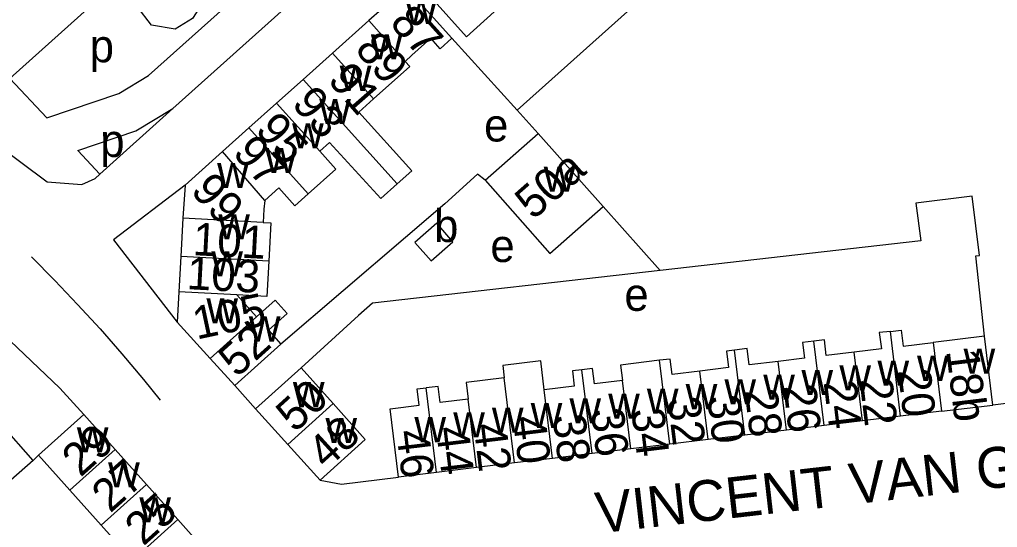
# Model space of a CAD drawing. Extents: x 161775 to 163181, y 382878 to 383925.
# Drawn here: x 162735.4 to 162855, y 383267.3 to 383329.4 of the extents above; entities that cross this region are included whole.
import ezdxf

# ---------------------------------------------------------------- set-up
doc = ezdxf.new("R2010")
doc.units = 0
for name, color, linetype in [('BLT_Basislijn', 7, 'Continuous'), ('BLT_Bebouwing', 7, 'Continuous'), ('BLT_Centroide', 7, 'Continuous'), ('BLT_Huisnummer', 7, 'Continuous'), ('BLT_Huisnummer_ tussenligend', 7, 'Continuous'), ('BLT_Onderverdeling_panden', 7, 'Continuous'), ('BLT_Straatnaam', 7, 'Continuous')]:
    doc.layers.add(name, color=color, linetype=linetype)

msp = doc.modelspace()

# ---------------------------------------------------------------- linework, layer by layer
at = {"layer": 'BLT_Basislijn'}
for p, q in [((162796.22, 383318.34), (162857.79, 383373.53)), ((162751.13, 383322.57), (162767.53, 383337.28)), ((162734.18, 383322.22), (162747.65, 383334.31)), ((162754.11, 383318.53), (162771.38, 383334.03)), ((162796.22, 383318.34), (162788.22, 383327.14)), ((162734.18, 383322.22), (162738.71, 383317.41)), ((162745.19, 383310.52), (162754.11, 383318.53)), ((162798.8, 383315.5), (162796.22, 383318.34)), ((162742.48, 383313.4), (162745.19, 383310.52)), ((162744.61, 383310), (162745.19, 383310.52)), ((162792.31, 383309.78), (162791.36, 383310.5)), ((162806.75, 383306.55), (162813.73, 383298.72)), ((162776.82, 383293.21), (162769.8, 383286.82)), ((162764.23, 383281.8), (162761.68, 383284.66)), ((162861.08, 383283.08), (162854.42, 383282.27)), ((162737.68, 383276.13), (162737.02, 383275.48))]:
    msp.add_line(p, q, dxfattribs=at)
for points in [[(162762.22, 383347.39), (162765.35, 383344.2), (162765.81, 383341.08), (162763.37, 383335.52), (162762.16, 383333.95), (162760.51, 383332.85), (162759.35, 383332.56), (162757.88, 383331.64), (162756.53, 383329.54), (162754.39, 383328.24), (162751.51, 383328.73), (162749.75, 383331.04), (162747.65, 383334.31)], [(162738.71, 383317.41), (162747.49, 383320.39), (162751.13, 383322.57)], [(162732.32, 383320.55), (162731.35, 383318.86), (162732.27, 383314.38), (162738.74, 383309.56), (162742.97, 383309.23)], [(162742.48, 383313.4), (162749.6, 383315.82), (162754.11, 383318.53)], [(162791.36, 383310.5), (162787.37, 383306.9), (162782.58, 383302.75), (162767.34, 383289.73)], [(162742.97, 383309.23), (162744.61, 383310)], [(162755.6, 383309.17), (162746.86, 383302.49), (162754.64, 383292.41)], [(162853.39, 383290.69), (162852.32, 383300.52), (162852.76, 383300.57), (162851.87, 383307.83), (162844.97, 383306.97), (162845.61, 383302.36), (162813.73, 383298.72)], [(162736.81, 383300.4), (162739.67, 383297.51), (162742.47, 383294.57), (162745.21, 383291.57), (162747.89, 383288.51), (162750.51, 383285.41), (162752.57, 383282.87)], [(162813.73, 383298.72), (162778.52, 383294.73), (162776.82, 383293.21)], [(162730.7, 383293.41), (162740.29, 383284.35), (162743.22, 383281.09)], [(162772.15, 383273.06), (162774.76, 383272.58), (162781.73, 383273.46)]]:
    msp.add_lwpolyline(points, dxfattribs=at)
at = {"layer": 'BLT_Bebouwing'}
for p, q in [((162790.02, 383327.33), (162783.75, 383334.33)), ((162782.64, 383333.39), (162778.08, 383329.31)), ((162788.22, 383327.14), (162782.64, 383333.39)), ((162794.67, 383331.51), (162790.02, 383327.33)), ((162778.08, 383329.31), (162773.63, 383325.32)), ((162773.63, 383325.32), (162770.04, 383322.1)), ((162770.04, 383322.1), (162766.79, 383319.2)), ((162766.79, 383319.2), (162763.41, 383316.17)), ((162763.41, 383316.17), (162760.17, 383313.27)), ((162792.31, 383309.78), (162798.8, 383315.5)), ((162798.8, 383315.5), (162806.75, 383306.55)), ((162792.31, 383309.78), (162800.22, 383300.8)), ((162800.22, 383300.8), (162806.75, 383306.55)), ((162755.34, 383305.12), (162755.09, 383300.43)), ((162755.09, 383300.43), (162754.85, 383296.11)), ((162754.85, 383296.11), (162754.64, 383292.41)), ((162761.93, 383295.74), (162764.36, 383293.05)), ((162754.64, 383292.41), (162758.69, 383287.95)), ((162853.39, 383290.69), (162847.11, 383289.91)), ((162854.42, 383282.27), (162853.39, 383290.69)), ((162761.68, 383284.66), (162767.34, 383289.73)), ((162758.69, 383287.95), (162761.68, 383284.66)), ((162764.23, 383281.8), (162769.8, 383286.82)), ((162769.8, 383286.82), (162773.71, 383282.46)), ((162768.19, 383277.43), (162764.23, 383281.8)), ((162848.13, 383281.51), (162843.12, 383280.9)), ((162848.13, 383281.51), (162854.42, 383282.27)), ((162737.68, 383276.13), (162743.22, 383281.09)), ((162743.22, 383281.09), (162747.05, 383276.82)), ((162838.46, 383280.33), (162833.79, 383279.77)), ((162843.12, 383280.9), (162838.46, 383280.33)), ((162829.16, 383279.21), (162824.07, 383278.59)), ((162833.79, 383279.77), (162829.16, 383279.21)), ((162819.58, 383278.04), (162814.9, 383277.48)), ((162824.07, 383278.59), (162819.58, 383278.04)), ((162747.05, 383276.82), (162750.88, 383272.54)), ((162772.15, 383273.06), (162768.19, 383277.43)), ((162810.11, 383276.9), (162805.38, 383276.32)), ((162814.9, 383277.48), (162810.11, 383276.9)), ((162741.51, 383271.86), (162737.68, 383276.13)), ((162800.56, 383275.74), (162795.92, 383275.18)), ((162805.38, 383276.32), (162800.56, 383275.74)), ((162791.24, 383274.61), (162786.37, 383274.02)), ((162795.92, 383275.18), (162791.24, 383274.61)), ((162786.37, 383274.02), (162781.73, 383273.46)), ((162750.88, 383272.54), (162754.71, 383268.26)), ((162745.34, 383267.58), (162741.51, 383271.86)), ((162749.17, 383263.3), (162745.34, 383267.58)), ((162754.71, 383268.26), (162758.54, 383263.98))]:
    msp.add_line(p, q, dxfattribs=at)
for points in [[(162788.22, 383327.14), (162786.81, 383325.86), (162785.68, 383327.14), (162783.36, 383325.05)], [(162783.36, 383325.05), (162782.54, 383324.31)], [(162782.54, 383324.31), (162783.08, 383323.7), (162778.66, 383319.73)], [(162778.66, 383319.73), (162776.87, 383318.11), (162783.34, 383310.93), (162781.54, 383309.31)], [(162781.54, 383309.31), (162779.56, 383307.52), (162773.27, 383314.38), (162772.08, 383313.31)], [(162760.17, 383313.27), (162755.6, 383309.17)], [(162772.08, 383313.31), (162774.04, 383311.14), (162770.67, 383308.1)], [(162755.6, 383309.17), (162755.34, 383305.12)], [(162770.67, 383308.1), (162769.04, 383306.64), (162767.08, 383308.83), (162765.37, 383307.29)], [(162765.37, 383307.29), (162765.24, 383306.23), (162765.16, 383304.61)], [(162765.16, 383304.61), (162766.09, 383304.56), (162765.84, 383299.86)], [(162765.84, 383299.86), (162765.61, 383295.54), (162761.93, 383295.74)], [(162764.36, 383293.05), (162766.63, 383295.09), (162768.09, 383293.46), (162765.82, 383291.42), (162767.34, 383289.73)], [(162841.87, 383291.28), (162840.52, 383291.12), (162840.77, 383289.14), (162837.43, 383288.73)], [(162841.87, 383291.28), (162843.19, 383291.44), (162843.43, 383289.47), (162847.11, 383289.91)], [(162832.53, 383290.1), (162831.12, 383289.93), (162831.36, 383287.99), (162828.14, 383287.6)], [(162837.43, 383288.73), (162834.03, 383288.32), (162833.8, 383290.25), (162832.53, 383290.1)], [(162822.8, 383288.99), (162821.83, 383288.87), (162822.07, 383286.86), (162818.56, 383286.43)], [(162828.14, 383287.6), (162824.61, 383287.17), (162824.36, 383289.18), (162822.8, 383288.99)], [(162799.54, 383284.11), (162799.11, 383287.66), (162794.47, 383287.1), (162794.65, 383285.59)], [(162813.65, 383287.74), (162808.86, 383287.15), (162809.09, 383285.28)], [(162818.56, 383286.43), (162815.17, 383286.02), (162814.94, 383287.89), (162813.65, 383287.74)], [(162804.13, 383286.58), (162802.98, 383286.44), (162803.21, 383284.56), (162799.54, 383284.11)], [(162809.09, 383285.28), (162805.67, 383284.86), (162805.44, 383286.74), (162804.13, 383286.58)], [(162794.65, 383285.59), (162789.97, 383285.02), (162790.22, 383282.98)], [(162781.73, 383273.46), (162780.71, 383281.82), (162784.23, 383282.25), (162783.99, 383284.23), (162785.1, 383284.37)], [(162790.22, 383282.98), (162786.79, 383282.56), (162786.55, 383284.55), (162785.1, 383284.37)], [(162773.71, 383282.46), (162777.65, 383278.07), (162772.15, 383273.06)], [(162737.02, 383275.48), (162733.14, 383279.88), (162732.2, 383279.1), (162726.19, 383278.83), (162724.44, 383277.29), (162723.16, 383278.8), (162722.03, 383277.81)], [(162737.02, 383275.48), (162733.27, 383272.17), (162728.26, 383267.75)]]:
    msp.add_lwpolyline(points, dxfattribs=at)
msp.add_lwpolyline([(162786.4, 383304.52), (162783.72, 383302.14), (162785.71, 383299.9), (162788.37, 383302.25)], close=True, dxfattribs=at)
at = {"layer": 'BLT_Onderverdeling_panden'}
for p, q in [((162782.54, 383324.31), (162778.08, 383329.31)), ((162778.66, 383319.73), (162773.63, 383325.32)), ((162781.54, 383309.31), (162770.04, 383322.1)), ((162772.08, 383313.31), (162766.79, 383319.2)), ((162770.67, 383308.1), (162763.41, 383316.17)), ((162765.37, 383307.29), (162760.17, 383313.27)), ((162765.16, 383304.61), (162755.34, 383305.12)), ((162765.84, 383299.86), (162755.09, 383300.43)), ((162761.93, 383295.74), (162754.85, 383296.11)), ((162764.36, 383293.05), (162758.69, 383287.95)), ((162843.12, 383280.9), (162841.87, 383291.28)), ((162833.79, 383279.77), (162832.53, 383290.1)), ((162847.11, 383289.91), (162848.13, 383281.51)), ((162824.07, 383278.59), (162822.8, 383288.99)), ((162838.46, 383280.33), (162837.43, 383288.73)), ((162814.9, 383277.48), (162813.65, 383287.74)), ((162829.16, 383279.21), (162828.14, 383287.6)), ((162805.38, 383276.32), (162804.13, 383286.58)), ((162819.58, 383278.04), (162818.56, 383286.43)), ((162795.92, 383275.18), (162794.65, 383285.59)), ((162810.11, 383276.9), (162809.09, 383285.28)), ((162786.37, 383274.02), (162785.1, 383284.37)), ((162800.56, 383275.74), (162799.54, 383284.11)), ((162791.24, 383274.61), (162790.22, 383282.98)), ((162773.71, 383282.46), (162768.19, 383277.43)), ((162741.51, 383271.86), (162747.05, 383276.82)), ((162745.34, 383267.58), (162750.88, 383272.54)), ((162749.17, 383263.3), (162754.71, 383268.26))]:
    msp.add_line(p, q, dxfattribs=at)

# ---------------------------------------------------------------- texts
at = {"layer": 'BLT_Centroide'}
for s, p in [('w', (162782.55, 383328.88)), ('p', (162743.94, 383324.2)), ('w', (162778.33, 383324.56)), ('w', (162774.53, 383320.7)), ('w', (162772.02, 383316.64)), ('e', (162792.18, 383314.51)), ('w', (162768.7, 383313.67)), ('p', (162745.23, 383312.61)), ('w', (162765.41, 383310.64)), ('w', (162759.53, 383308.81)), ('w', (162799.47, 383308.36)), ('w', (162759.67, 383302.53)), ('b', (162786.06, 383302.21)), ('e', (162792.95, 383299.76)), ('w', (162758.82, 383298)), ('e', (162809.34, 383293.79)), ('w', (162758.22, 383292.25)), ('w', (162763.41, 383290.03)), ('w', (162850.83, 383286.09)), ('w', (162840.3, 383284.62)), ('w', (162845.14, 383285.22)), ('w', (162831, 383283.48)), ('w', (162835.64, 383284.05)), ('w', (162821.58, 383282.34)), ('w', (162826.33, 383282.91)), ('w', (162768.8, 383282)), ('w', (162812.09, 383281.19)), ('w', (162816.84, 383281.75)), ('w', (162802.62, 383280.03)), ('w', (162807.36, 383280.59)), ('w', (162793.14, 383278.88)), ('w', (162797.88, 383279.45)), ('w', (162772.78, 383277.62)), ('w', (162783.66, 383277.72)), ('w', (162788.41, 383278.3)), ('w', (162742.37, 383276.47)), ('w', (162746.2, 383272.19)), ('w', (162750.02, 383267.91))]:
    msp.add_text(s, height=4, dxfattribs=at).set_placement(p)
at = {"layer": 'BLT_Huisnummer'}
for s, rotation, p in [('87', 312.0034, (162780.51, 383328.93)), ('91', 311.1647, (162772.93, 383321.96)), ('95', 311.1657, (162764.06, 383315.85)), ('50a', 41.3673, (162798.19, 383304.82)), ('99', 311.9888, (162756.16, 383308.4)), ('103', 356.9917, (162755.76, 383296.45)), ('52', 41.9905, (162761.95, 383285.53)), ('18b', 276.9462, (162848.7, 383288.9)), ('50', 42.3364, (162769.02, 383278.79)), ('22', 276.947, (162838.08, 383285.42)), ('26', 276.9538, (162828.76, 383284.6)), ('30', 276.9538, (162819.45, 383283.26)), ('34', 276.9538, (162810.18, 383281.68)), ('48', 42.3364, (162772.89, 383274.29)), ('38', 276.9538, (162800.55, 383280.92)), ('29', 41.8332, (162742.81, 383273.35)), ('42', 276.953, (162790.88, 383279.84)), ('46', 276.9488, (162781.43, 383279.04)), ('25', 41.8332, (162750.5, 383264.93))]:
    msp.add_text(s, height=4, rotation=rotation, dxfattribs=at).set_placement(p)
at = {"layer": 'BLT_Huisnummer_ tussenligend'}
for s, rotation, p in [('89', 311.1647, (162776.25, 383325.71)), ('93', 311.1657, (162768.53, 383319.05)), ('97', 311.9888, (162761.3, 383313.03)), ('101', 356.9917, (162756.49, 383300.61)), ('105', 11.9893, (162757.02, 383290.26)), ('20', 276.947, (162842.77, 383286.5)), ('24', 276.9538, (162833.7, 383285.07)), ('28', 276.9538, (162824.03, 383284.06)), ('32', 276.9538, (162814.6, 383283.06)), ('36', 276.9538, (162805.23, 383281.67)), ('40', 276.953, (162795.67, 383280.76)), ('44', 276.953, (162786.28, 383279.46)), ('27', 41.8332, (162746.45, 383268.97))]:
    msp.add_text(s, height=4, rotation=rotation, dxfattribs=at).set_placement(p)
at = {"layer": 'BLT_Straatnaam'}
msp.add_text('VINCENT VAN GOGHSTRAAT', height=5, rotation=6.5128, dxfattribs=at).set_placement((162806.13, 383266.55))

doc.saveas('drawing.dxf')
